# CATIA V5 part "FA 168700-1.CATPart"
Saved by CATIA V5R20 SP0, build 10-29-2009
Part number: FA 168700-1
Revision: ANY
Definition: UNKNOWN
Nomenclature: FA 168700-1
Source: Unknown
Bounding box of the stored display mesh (mm): x -3.804 to 3.804, y 0.28 to 2.5, z -4 to 4
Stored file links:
  C:\Users\Utente\Desktop\IO LAVORO\3D X SITO CF\CUMSA\3D files FA\FA 1687SF\FA 168700-1.CATPart

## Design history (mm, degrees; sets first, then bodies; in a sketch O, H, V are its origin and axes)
Body1 "Cortar-Extruir1" (main body)
  Solid1: solid without history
